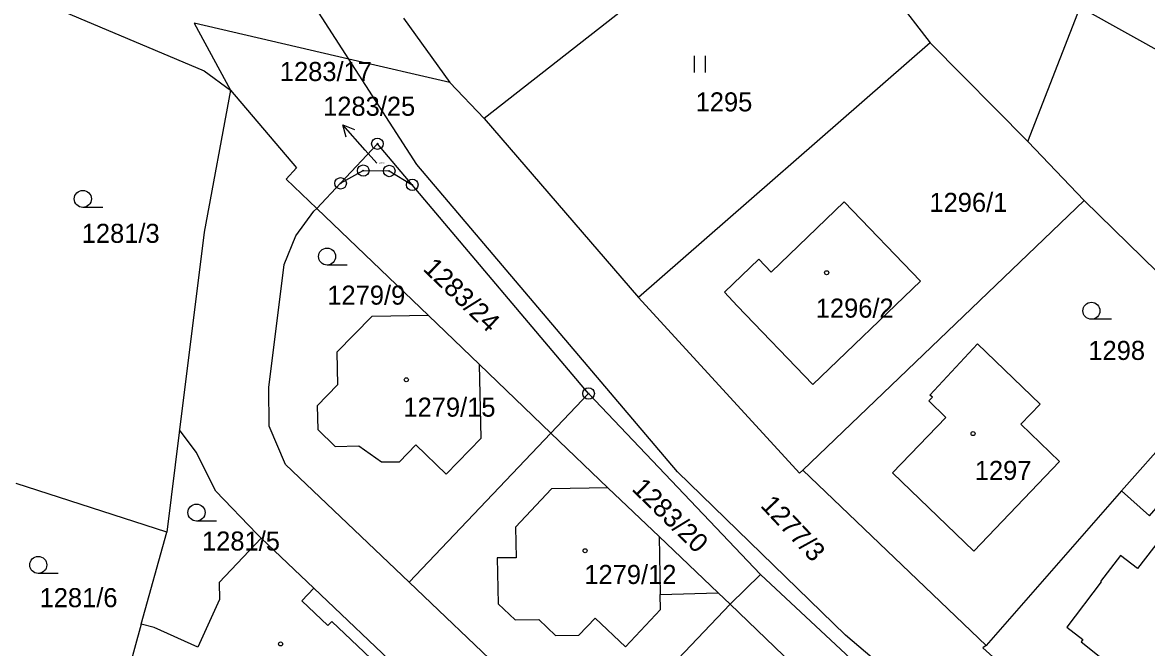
# Model space of a CAD drawing. Extents: x -737240 to -735272, y -1119606 to -1117878.
# Drawn here: x -735996.5 to -735896.2, y -1119084.5 to -1119028.8 of the extents above; entities that cross this region are included whole.
import ezdxf

# ---------------------------------------------------------------- set-up
doc = ezdxf.new("R2010")
doc.units = 0
for name, color, linetype in [('Level 1', 7, 'Continuous'), ('Level 16', 7, 'Continuous'), ('Level 18', 7, 'Continuous'), ('Level 19', 7, 'Continuous'), ('Level 25', 7, 'Continuous'), ('Level 4', 7, 'Continuous')]:
    doc.layers.add(name, color=color, linetype=linetype)

msp = doc.modelspace()

# ---------------------------------------------------------------- linework, layer by layer
at = {"layer": 'Level 1'}
for p, q in [((-735927.2, -1119015.36), (-735955.3, -1119037.34)), ((-735927.2, -1119015.36), (-735915.48, -1119030.61)), ((-735906.78, -1119039.39), (-735902.11, -1119027.41)), ((-735902.11, -1119027.41), (-735880.89, -1119039.29)), ((-735962.47, -1119028.4), (-735958.34, -1119034.15)), ((-735915.48, -1119030.61), (-735941.51, -1119053.31)), ((-735915.48, -1119030.61), (-735906.78, -1119039.39)), ((-735958.34, -1119034.15), (-735967.35, -1119032.06)), ((-735958.34, -1119034.15), (-735955.3, -1119037.34)), ((-735955.3, -1119037.34), (-735941.51, -1119053.31)), ((-735906.78, -1119039.39), (-735901.77, -1119044.67)), ((-735968.09, -1119043.13), (-735970.2, -1119045.39)), ((-735945.97, -1119061.87), (-735961.7, -1119043.27)), ((-735970.2, -1119045.39), (-735960.24, -1119054.92)), ((-735901.77, -1119044.67), (-735926.86, -1119068.71)), ((-735901.77, -1119044.67), (-735887.69, -1119058.43)), ((-735960.24, -1119054.92), (-735955.71, -1119059.29)), ((-735955.71, -1119059.29), (-735949.35, -1119065.42)), ((-735949.35, -1119065.42), (-735945.97, -1119061.87)), ((-735930.64, -1119078.02), (-735945.97, -1119061.87)), ((-735982.46, -1119065.1), (-735983.61, -1119074.25)), ((-735961.99, -1119078.69), (-735949.35, -1119065.42)), ((-735949.35, -1119065.42), (-735944.26, -1119070.29)), ((-735893.78, -1119065.31), (-735898.43, -1119070.56)), ((-735926.86, -1119068.71), (-735910.51, -1119084.34)), ((-735983.61, -1119074.25), (-735997.04, -1119069.91)), ((-735944.26, -1119070.29), (-735939.68, -1119074.64)), ((-735898.43, -1119070.56), (-735910.51, -1119084.34)), ((-735985.88, -1119082.43), (-735983.61, -1119074.25)), ((-735939.68, -1119074.64), (-735934.41, -1119079.66)), ((-735970.47, -1119079.23), (-735975.18, -1119074.76)), ((-735945.98, -1119093.93), (-735961.99, -1119078.69)), ((-735930.64, -1119078.02), (-735933.35, -1119080.67)), ((-735914.57, -1119092.95), (-735930.64, -1119078.02)), ((-735959.2, -1119089.95), (-735970.47, -1119079.23)), ((-735939.57, -1119079.8), (-735934.41, -1119079.66)), ((-735934.41, -1119079.66), (-735933.35, -1119080.67)), ((-735945.98, -1119093.93), (-735933.35, -1119080.67)), ((-735933.35, -1119080.67), (-735917.39, -1119095.95)), ((-735985.88, -1119082.43), (-735987.31, -1119087.59))]:
    msp.add_line(p, q, dxfattribs=at)
for points in [[(-735967.35, -1119032.06), (-735975.1, -1119020.06), (-735994.4, -1118984.85), (-736003.91, -1118966.89), (-736011.62, -1118950.01), (-736017.65, -1118934.07)], [(-736002.21, -1119022.91), (-736002, -1119022.98), (-735993.95, -1119027.32), (-735980.26, -1119033.09), (-735977.91, -1119034.81)], [(-735967.35, -1119032.06), (-735981.15, -1119028.86), (-735977.91, -1119034.81)], [(-735900.65, -1119102.37), (-735901.22, -1119101.96), (-735923.06, -1119083.43), (-735938.04, -1119068.85), (-735961.28, -1119041.45), (-735967.35, -1119032.06)], [(-735977.91, -1119034.81), (-735980.26, -1119047.5), (-735982.46, -1119065.1)], [(-735977.91, -1119034.81), (-735972.04, -1119041.75), (-735972.96, -1119042.76), (-735970.2, -1119045.39)], [(-735961.7, -1119043.27), (-735964.81, -1119039.6), (-735968.09, -1119043.13)], [(-735968.09, -1119043.13), (-735966.07, -1119042), (-735963.75, -1119042.03), (-735961.7, -1119043.27)], [(-735961.99, -1119078.69), (-735973, -1119068.21), (-735974.48, -1119064.78), (-735974.51, -1119061.33), (-735973.14, -1119050.37), (-735972.1, -1119047.81), (-735970.47, -1119045.6), (-735970.2, -1119045.39)], [(-735916.36, -1119051.87), (-735923.16, -1119044.79), (-735929.67, -1119051.04), (-735930.77, -1119049.89), (-735933.85, -1119052.85), (-735932.71, -1119054.05), (-735925.95, -1119061.08), (-735916.36, -1119051.87)], [(-735941.51, -1119053.31), (-735927.14, -1119068.97), (-735926.86, -1119068.71)], [(-735960.24, -1119054.92), (-735965.31, -1119055.01), (-735968.43, -1119058.2), (-735968.36, -1119061.1), (-735970.18, -1119062.97), (-735970.14, -1119065.09), (-735968.57, -1119066.59), (-735966.47, -1119066.54), (-735964.44, -1119067.97), (-735962.84, -1119067.96), (-735961.38, -1119066.46), (-735958.69, -1119069.07), (-735955.56, -1119065.85), (-735955.71, -1119059.29)], [(-735903.96, -1119067.95), (-735911.61, -1119075.92), (-735918.87, -1119068.96), (-735914.09, -1119064), (-735915.61, -1119062.54), (-735915.28, -1119062.2), (-735915.52, -1119062.02), (-735911.28, -1119057.43), (-735905.68, -1119062.82), (-735907.42, -1119064.62), (-735903.96, -1119067.95)], [(-735975.18, -1119074.76), (-735975.57, -1119074.39), (-735979.24, -1119070.59), (-735980.98, -1119067.1), (-735982.46, -1119065.1)], [(-735898.43, -1119070.56), (-735895.93, -1119072.77), (-735891.31, -1119067.5), (-735893.78, -1119065.31)], [(-735944.26, -1119070.29), (-735949.27, -1119070.37), (-735952.48, -1119073.78), (-735952.42, -1119076.52), (-735954.14, -1119076.54), (-735954.05, -1119080.62), (-735952.51, -1119082.07), (-735950.42, -1119082.02), (-735948.93, -1119083.46), (-735946.84, -1119083.43), (-735945.38, -1119081.9), (-735942.67, -1119084.46), (-735939.54, -1119081.14), (-735939.57, -1119079.8)], [(-735975.18, -1119074.76), (-735978.94, -1119078.73), (-735978.9, -1119080.25), (-735980.82, -1119084.5), (-735984.73, -1119082.75), (-735985.88, -1119082.43)], [(-735900.24, -1119078.68), (-735903.3, -1119082.72), (-735901.87, -1119083.82), (-735902.03, -1119084.02), (-735899.68, -1119085.9), (-735899.28, -1119085.4), (-735895.97, -1119088.02), (-735896.37, -1119088.52), (-735893.81, -1119090.56), (-735886.46, -1119081.34), (-735894.85, -1119074.71), (-735897, -1119077.49), (-735898.52, -1119076.31), (-735900.3, -1119078.63), (-735900.24, -1119078.68)], [(-735967.95, -1119096.22), (-735961.39, -1119089.32), (-735968.87, -1119082.2), (-735969.22, -1119082.57), (-735971.54, -1119080.35), (-735970.47, -1119079.23)], [(-735910.51, -1119084.34), (-735910.81, -1119084.55), (-735906.03, -1119088.82), (-735902.15, -1119092.17), (-735899.17, -1119094.37), (-735898.26, -1119095)]]:
    msp.add_lwpolyline(points, dxfattribs=at)
at = {"layer": 'Level 16'}
for points in [[(-735967.602, -1119039.007), (-735967.893, -1119037.927), (-735966.855, -1119038.343)], [(-735964.86, -1119041.34), (-735965.9, -1119040.17), (-735967.893, -1119037.927)]]:
    msp.add_lwpolyline(points, dxfattribs=at)
at = {"layer": 'Level 25'}
for p, q in [((-735936.547, -1119031.755), (-735936.547, -1119033.255)), ((-735935.525, -1119033.255), (-735935.525, -1119031.755)), ((-735989.308, -1119045.28), (-735991.09, -1119045.28)), ((-735967.518, -1119050.42), (-735969.3, -1119050.42)), ((-735899.328, -1119055.25), (-735901.11, -1119055.25)), ((-735979.168, -1119073.25), (-735980.95, -1119073.25)), ((-735993.288, -1119077.92), (-735995.07, -1119077.92))]:
    msp.add_line(p, q, dxfattribs=at)
for centre, major_axis, ratio in [((-735964.81, -1119039.6), (0.516, 0), 0.9848078), ((-735964.81, -1119039.6), (0.0375, 0), 0.9848078), ((-735966.07, -1119042), (0.516, 0), 0.9848078), ((-735963.75, -1119042.03), (0.516, 0), 0.9848078), ((-735966.07, -1119042), (0.0375, 0), 0.9848078), ((-735963.75, -1119042.03), (0.0375, 0), 0.9848078), ((-735968.09, -1119043.13), (0.516, 0), 0.9848078), ((-735968.09, -1119043.13), (0.0375, 0), 0.9848078), ((-735961.7, -1119043.27), (0.516, 0), 0.9848078), ((-735961.7, -1119043.27), (0.0375, 0), 0.9848078), ((-735991.09, -1119044.524), (0.764, 0), 0.9894236), ((-735969.3, -1119049.664), (0.764, 0), 0.9894236), ((-735924.73, -1119051.1), (0.18, 0), 0.9848078), ((-735901.11, -1119054.494), (0.764, 0), 0.9894236), ((-735962.23, -1119060.65), (0.18, 0), 0.9848078), ((-735945.97, -1119061.87), (0.516, 0), 0.9848078), ((-735945.97, -1119061.87), (0.0375, 0), 0.9848078), ((-735911.67, -1119065.45), (0.18, 0), 0.9848078), ((-735980.95, -1119072.494), (0.764, 0), 0.9894236), ((-735995.07, -1119077.164), (0.764, 0), 0.9894236), ((-735946.28, -1119075.89), (0.18, 0), 0.9848078), ((-735973.45, -1119084.21), (0.18, 0), 0.9848078)]:
    msp.add_ellipse(centre, major_axis=major_axis, ratio=ratio, dxfattribs=at)
at = {"layer": 'Level 4'}
msp.add_line((-735939.68, -1119074.64), (-735939.57, -1119079.8), dxfattribs=at)

# ---------------------------------------------------------------- texts
at = {"layer": 'Level 16'}
msp.add_text('1283/25', height=1.7, dxfattribs=at).set_placement((-735969.655, -1119037.11))
at = {"layer": 'Level 18'}
for s, height, p in [('1283/17', 1.7, (-735973.515, -1119034.01)), ('1295', 1.7, (-735936.42, -1119036.72)), ('1283/25', 0.1, (-735964.685, -1119041.34)), ('1296/1', 1.7, (-735915.56, -1119045.68)), ('1281/3', 1.7, (-735991.19, -1119048.44)), ('1279/9', 1.7, (-735969.28, -1119053.95)), ('1298', 1.7, (-735901.38, -1119058.88)), ('1281/5', 1.7, (-735980.46, -1119075.88)), ('1281/6', 1.7, (-735994.95, -1119080.93))]:
    msp.add_text(s, height=height, dxfattribs=at).set_placement(p)
for s, rotation, p in [('1283/24', 316.14147, (-735960.835, -1119050.831)), ('1283/20', 315.54567, (-735942.196, -1119070.454)), ('1277/3', 313.09812, (-735930.708, -1119071.922))]:
    msp.add_text(s, height=1.7, rotation=rotation, dxfattribs=at).set_placement(p)
at = {"layer": 'Level 19'}
for s, p in [('1296/2', (-735925.705, -1119055.11)), ('1279/15', (-735962.49, -1119063.94)), ('1297', (-735911.515, -1119069.58)), ('1279/12', (-735946.35, -1119078.86))]:
    msp.add_text(s, height=1.7, dxfattribs=at).set_placement(p)

doc.saveas('drawing.dxf')
